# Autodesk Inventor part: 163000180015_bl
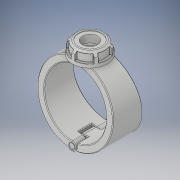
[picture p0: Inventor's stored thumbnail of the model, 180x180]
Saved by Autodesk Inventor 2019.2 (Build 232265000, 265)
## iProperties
Created: 2022-02
Part Number: 163000180015_bl
Material: Generic
Description: Plassadle Threaded 180x1 1/2''
Document SubType Name: Modeling
Designer: comp2
Density: 1 g/cm^3
Appearance: Default
Author: comp2
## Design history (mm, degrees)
derived "16300.ipt"
feature "Solid1::16300.ipt" dims "ScaleForDerivedMember" = 10
feature "Solid2::16300.ipt" dims "ScaleForDerivedMember" = 10
feature "Solid3::16300.ipt" dims "ScaleForDerivedMember" = 10
feature "Solid4::16300.ipt" dims "ScaleForDerivedMember" = 10
tag "TaggingFeature1"
body "Solid1"
body "Solid2"
body "Solid3"
body "Solid4"
other parameters: "d1" = 25 [user parameter], "E_" = 54 [user parameter], "E1" = 102 [user parameter], "H1" = 255 [user parameter], "H2" = 49 [user parameter], "H3" = 78 [user parameter], "H_costum" = 49 [user parameter], "Rp" = 44.845 [user parameter], "d128" = 36.1 [user parameter], "d7" = 209 [user parameter], "d8" = 85 deg [user parameter], "d9" = 45 deg [user parameter], "d10" = 102 [user parameter], "d11" = 49 [user parameter], "d12" = 25.27 [user parameter], "d13" = 42.84 [user parameter], "d14" = 67.2675 [user parameter], "d42" = 4 [user parameter], "d49" = 4.4 [user parameter], "d51" = 0 [user parameter], "d52" = 28 [user parameter], "d53" = 121 [user parameter], "d54" = 38.5 [user parameter], "d55" = 0 [user parameter], "d56" = 22 [user parameter], "d57" = 22 [user parameter], "d59" = 0 [user parameter], "d61" = 0 [user parameter], "d62" = 38.5 [user parameter], "d63" = 0 [user parameter], "d65" = 0 [user parameter], "d67" = 0 [user parameter], "d69" = 0 [user parameter], "d70" = 1 [user parameter], "d71" = 105.6 [user parameter], "d72" = 0 [user parameter], "d73" = 2 [user parameter], "d78" = 86.7 [user parameter], "d79" = 5.1 [user parameter], "d80" = 60 deg [user parameter], "d81" = 5.1 [user parameter], "d84" = 0 [user parameter], "d85" = 1 [user parameter], "d87" = 360 deg [user parameter], "d122" = 49 [user parameter], "d124" = 42.80128 [user parameter], "d125" = 1.805 [user parameter], "d127" = 255 [user parameter], "d129" = 44.845 [user parameter], "d130" = 38.11825 [user parameter], "d131" = 31.85 [user parameter], "d132" = 45 deg [user parameter], "d133" = 22.295 [user parameter], "d134" = 22.4225 [user parameter], "d136" = 0 [user parameter], "d138" = 0 [user parameter]
